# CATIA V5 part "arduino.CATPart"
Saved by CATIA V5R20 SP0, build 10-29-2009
Part number: arduino2
Bounding box of the stored display mesh (mm): x -20.66 to 70.72, y -123.76 to 0, z -5.9 to 1.5
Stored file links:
  C:\Users\user\OneDrive\바탕 화면\지혜 카티아\arduino2.CATPart
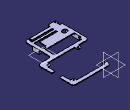
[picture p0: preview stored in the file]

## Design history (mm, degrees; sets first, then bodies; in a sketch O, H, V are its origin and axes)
Sketch1 on xy-plane, origin (0, 0, 0), H (1, 0, 0), V (0, 1, 0)
  line L1 (0, 0) -> (70.72, 0)
  line L2 (0, 0) -> (0, -12)
  line L3 (0, -12) -> (6, -12)
  line L4 (6, -12) -> (6, -6)
  line L5 (6, -6) -> (58.3, -6)
  line L6 (58.3, -6) -> (58.3, -11.85)
  line L7 (58.3, -11.85) -> (64.72, -11.85)
  line L8 (64.72, -11.85) -> (64.72, -55.31)
  line L9 (64.72, -55.31) -> (57.76, -55.31)
  line L10 (57.76, -55.31) -> (57.76, -62.09)
  line L11 (57.76, -62.09) -> (6.57, -62.09)
  line L12 (6.57, -62.09) -> (6.57, -55.52)
  line L13 (6.57, -55.52) -> (0, -55.52)
  line L14 (0, -55.52) -> (0, -68.09)
  line L15 (0, -68.09) -> (70.72, -68.09)
  line L16 (70.72, -68.09) -> (70.72, 0)
  distance L2 L8 = 64.72
  distance L1 L5 = 6
  distance L8 L16 = 6
  distance L5 L11 = 56.09
  distance L14 L8 = 64.72
  distance L11 L15 = 6
  length L9 = 6.96
  length L10 = 6.78
  length L6 = 5.85
  length L7 = 6.42
  length L3 = 6
  length L4 = 6
  length L13 = 6.57
  length L12 = 6.57
  horizontal: L1 H, L3 H, L5 H, L7 H, L9 H, L11 H, L13 H, L15 H
  vertical: L2 V, L4 V, L6 V, L8 V, L10 V, L12 V, L14 V, L16 V
Pad1: profile Sketch1, direction (0, 0, 1), length 1.5
Body1 (main body)
  Sketch2 on end face of Pad1, origin (65.2584, -7.6318, 1.5), H (1, 0, 0), V (0, 1, 0)
    point P1 (-4.1484, -1.5282)
    reference projected line E1 (5.4616, 7.6318) -> (-65.2584, 7.6318) from edge [face of Pad1 from Sketch1.L1 | end face of Pad1]
    reference projected line E2 (5.4616, -60.4582) -> (5.4616, 7.6318) from edge [face of Pad1 from Sketch1.L16 | end face of Pad1]
    distance P1 E1 = 9.16
    distance P1 E2 = 9.61
  Hole1: placed by Sketch2, at (61.11, -9.16, 1.5) direction (0, 0, -1), diameter 2.73, depth 10
  Sketch3 on end face of Pad1, origin (2.6589, -8.6433, 1.5), H (1, 0, 0), V (0, 1, 0)
    point P1 (0.7611, -0.1967)
    reference projected line E1 (-2.6589, -3.3567) -> (3.3411, -3.3567) from edge [face of Pad1 from Sketch1.L3 | end face of Pad1]
    reference projected line E2 (68.0611, -59.4467) -> (68.0611, 8.6433) from edge [face of Pad1 from Sketch1.L16 | end face of Pad1]
    distance P1 E1 = 3.16
    distance P1 E2 = 67.3
  Hole2: placed by Sketch3, at (3.42, -8.84, 1.5) direction (0, 0, -1), diameter 2.73, depth 10
  Sketch4 on end face of Pad1, origin (60.9853, -58.9482, 1.5), H (1, 0, 0), V (0, 1, 0)
    point P1 (0.1347, 0.0182)
    reference projected line E1 (9.7347, -9.1418) -> (9.7347, 58.9482) from edge [face of Pad1 from Sketch1.L16 | end face of Pad1]
    reference projected line E2 (-60.9853, -9.1418) -> (9.7347, -9.1418) from edge [face of Pad1 from Sketch1.L15 | end face of Pad1]
    distance P1 E1 = 9.6
    distance P1 E2 = 9.16
  Hole3: placed by Sketch4, at (61.12, -58.93, 1.5) direction (0, 0, -1), diameter 2.73, depth 10
  Sketch5 on end face of Pad1, origin (3.2662, -58.7862, 1.5), H (1, 0, 0), V (0, 1, 0)
    point P1 (0.1538, 0.1062)
    reference projected line E1 (3.3038, 3.2662) -> (-3.2662, 3.2662) from edge [face of Pad1 from Sketch1.L13 | end face of Pad1]
    reference projected line E2 (67.4538, -9.3038) -> (67.4538, 58.7862) from edge [face of Pad1 from Sketch1.L16 | end face of Pad1]
    distance P1 E1 = 3.16
    distance P1 E2 = 67.3
  Hole4: placed by Sketch5, at (3.42, -58.68, 1.5) direction (0, 0, -1), diameter 2.73, depth 10
  Plane1: type Offset, RefPlane start face of Pad1, Offset 0, reversed
  Sketch6 on Plane1, origin (0, 0, 0), H (1, 0, 0), V (0, 1, 0)
    line L1 (44.92, -68.09) -> (44.92, -119.15)
    line L2 (44.92, -119.15) -> (33.92, -119.15)
    line L3 (33.92, -119.15) -> (33.92, -114.15)
    line L4 (33.92, -114.15) -> (38.92, -114.15)
    line L5 (38.92, -114.15) -> (38.92, -91.15)
    line L6 (38.92, -91.15) -> (33.92, -91.15)
    line L7 (33.92, -91.15) -> (33.92, -86.15)
    line L8 (33.92, -86.15) -> (38.92, -86.15)
    point P9 (38.92, -86.15)
    line L9 (38.92, -86.15) -> (38.92, -68.09)
    line L10 (38.92, -68.09) -> (44.92, -68.09)
    reference projected line E1 (0, -68.09) -> (70.72, -68.09) from edge [face of Pad1 from Sketch1.L15 | end face of Pad1]
    reference projected line E2 (70.72, -68.09) -> (70.72, 0) from edge [face of Pad1 from Sketch1.L16 | end face of Pad1]
    reference projected line E3 (0, -68.09) -> (70.72, -68.09) from edge [face of Pad1 from Sketch1.L15 | end face of Pad1]
    length L10 = 6
    distance L1 E2 = 25.8
    length L8 = 5
    distance L8 E3 = 18.06
    length L7 = 5
    length L4 = 5
    length L3 = 5
    distance L6 L2 = 28
    vertical: L1 V, L3 V, L5 V, L7 V
    horizontal: L2 H, L4 H, L6 H, L8 H, L10 H
    coincidence: P9 L5, L10 E1
    parallelism: L9 L1
  Pad2: profile Sketch6, direction (0, 0, 1), length 1.5
  Fillet1: radius 5, on edge [face of Pad1 from Sketch1.L15 | face of Pad1 from Sketch1.L14]; edge [face of Pad1 from Sketch1.L16 | face of Pad1 from Sketch1.L15]; edge [face of Pad1 from Sketch1.L1 | face of Pad1 from Sketch1.L16]; edge [face of Pad1 from Sketch1.L2 | face of Pad1 from Sketch1.L1]
  Fillet2: radius 2, on edge [face of Pad1 from Sketch1.L10 | face of Pad1 from Sketch1.L9]; edge [face of Pad1 from Sketch1.L7 | face of Pad1 from Sketch1.L6]; edge [face of Pad1 from Sketch1.L14 | face of Pad1 from Sketch1.L13]; edge [face of Pad1 from Sketch1.L13 | face of Pad1 from Sketch1.L12]; edge [face of Pad1 from Sketch1.L3 | face of Pad1 from Sketch1.L2]; edge [face of Pad1 from Sketch1.L4 | face of Pad1 from Sketch1.L3]
  Sketch7 on face of Pad2, origin (31.9797, -88.8903, 1.5), H (1, 0, 0), V (0, 1, 0)
    point P1 (4.4403, 0.2403)
    reference projected line E1 (1.9403, 2.7403) -> (1.9403, -2.2597) from edge [face of Pad2 from Sketch6.L7 | end face of Pad2]
    reference projected line E2 (2.7403, 2.7403) -> (-2.2597, 2.7403) from edge [face of Pad2 from Sketch6.L8 | end face of Pad2]
    distance P1 E1 = 2.5
    distance P1 E2 = 2.5
  Hole5: placed by Sketch7, at (36.42, -88.65, 1.5) direction (0, 0, -1), diameter 3.7, depth 10
  Sketch8 on face of Pad2, origin (31.9024, -116.9676, 1.5), H (1, 0, 0), V (0, 1, 0)
    point P1 (4.5176, 0.3176)
    reference projected line E1 (2.0176, 2.8176) -> (2.0176, -2.1824) from edge [face of Pad2 from Sketch6.L3 | end face of Pad2]
    reference projected line E2 (2.8176, 2.8176) -> (-2.1824, 2.8176) from edge [face of Pad2 from Sketch6.L4 | end face of Pad2]
    distance P1 E1 = 2.5
    distance P1 E2 = 2.5
  Hole6: placed by Sketch8, at (36.42, -116.65, 1.5) direction (0, 0, -1), diameter 3.7, depth 10
  Fillet3: radius 5, on edge [face of Pad2 from Sketch6.L1 | face of Pad2 from Sketch6.L2]
  Fillet4: radius 5, on edge [face of Pad1 from Sketch1.L15 | face of Pad2 from Sketch6.L1]; edge [face of Pad2 from Sketch6.L9 | face of Pad1 from Sketch1.L15]
  Sketch9 on face of Pad2, origin (0, 0, 1.5), H (1, 0, 0), V (0, 1, 0)
    line L1 (64.72, -28.51) -> (67.87, -28.51)
    line L2 (67.87, -28.51) -> (67.87, -39.58)
    line L3 (67.87, -39.58) -> (64.72, -39.58)
    line L4 (64.72, -39.58) -> (64.72, -28.51)
    reference projected line E1 (64.72, -11.85) -> (64.72, -55.31) from edge [face of Pad1 from Sketch1.L8 | end face of Pad1]
    reference projected line E2 (70.72, 0) -> (0, 0) from edge [face of Pad1 from Sketch1.L1 | face of Pad2]
    length L2 = 11.07
    length L1 = 3.15
    distance L1 E2 = 28.51
    horizontal: L1 H, L3 H
    vertical: L2 V, L4 V
    coincidence: L4 E1
  Pocket1: profile Sketch9, direction (0, 0, -1), length 1.5
  Sketch10 on Plane1, origin (0, 0, 0), H (1, 0, 0), V (0, 1, 0)
    line L1 (33.92, -86.15) -> (-16.43, -86.15)
    line L2 (-16.43, -86.15) -> (-16.43, -75.8188)
    line L3 (-16.43, -75.8188) -> (-12.89, -75.8188)
    line L4 (-12.89, -75.8188) -> (-12.89, -68.09)
    line L5 (-20.66, -69.4959) -> (-20.66, -112.93)
    line L6 (-20.66, -112.93) -> (-16.28, -112.93)
    line L7 (-16.28, -112.93) -> (-16.28, -118.03)
    line L8 (-16.28, -118.03) -> (-19.05, -118.03)
    line L9 (-19.05, -118.03) -> (-19.05, -123.76)
    line L10 (-19.05, -123.76) -> (-4.08, -123.76)
    line L11 (-4.08, -123.76) -> (-4.08, -119.15)
    line L12 (-4.08, -119.15) -> (33.92, -119.15)
    line L13 (33.92, -119.15) -> (33.92, -114.15)
    line L14 (33.92, -114.15) -> (-2.85, -114.15)
    line L15 (-2.85, -114.15) -> (-2.85, -110.67)
    line L16 (-2.85, -110.67) -> (38.92, -110.67)
    line L17 (38.92, -110.67) -> (38.92, -107.15)
    line L18 (38.92, -107.15) -> (-2.85, -107.15)
    point P20 (-2.85, -107.15)
    line L19 (-2.85, -107.15) -> (-2.85, -103.67)
    line L20 (-2.85, -103.67) -> (31.43, -103.67)
    line L21 (31.43, -103.67) -> (31.43, -91.15)
    line L22 (31.43, -91.15) -> (33.92, -91.15)
    line L23 (33.92, -91.15) -> (33.92, -86.15)
    reference projected line E1 (38.92, -86.15) -> (33.92, -86.15) from edge [face of Pad2 | face of Pad2 from Sketch6.L8]
    reference projected line E2 (33.92, -91.15) -> (38.92, -91.15) from edge [face of Pad2 | face of Pad2 from Sketch6.L6]
    reference projected line E3 (38.92, -114.15) -> (33.92, -114.15) from edge [start face of Pad2 | face of Pad2 from Sketch6.L4]
    reference projected line E4 (33.92, -119.15) -> (44.92, -119.15) from edge [face of Pad2 | face of Pad2 from Sketch6.L2]
    reference projected line E5 (38.92, -91.15) -> (38.92, -114.15) from edge [start face of Pad2 | face of Pad2 from Sketch6.L5]
    reference projected line E6 (33.92, -114.15) -> (33.92, -119.15) from edge [start face of Pad2 | face of Pad2 from Sketch6.L3]
    reference projected line E7 (33.92, -86.15) -> (33.92, -91.15) from edge [start face of Pad2 | face of Pad2 from Sketch6.L7]
    reference projected line E8 (38.92, -91.15) -> (38.92, -114.15) from edge [start face of Pad2 | face of Pad2 from Sketch6.L5]
    reference projected line E9 (38.92, -91.15) -> (38.92, -114.15) from edge [start face of Pad2 | face of Pad2 from Sketch6.L5]
    line L24 (-12.89, -68.09) -> (6.57, -68.09)
    line L25 (6.57, -68.09) -> (6.57, -62.09)
    line L26 (6.57, -62.09) -> (-20.66, -62.09)
    point P27 (-20.66, -62.09)
    line L27 (-20.66, -62.09) -> (-20.66, -69.4959)
    reference projected line E10 (44.92, -68.09) -> (70.72, -68.09) from edge [face of Pad2 | face of Pad1 from Sketch1.L15]
    reference projected line E12 (38.92, -68.09) -> (38.92, -86.15) from edge [face of Pad2 | face of Pad2 from Sketch6.L9]
    reference projected line E13 (38.92, -91.15) -> (38.92, -114.15) from edge [start face of Pad2 | face of Pad2 from Sketch6.L5]
    reference projected line E14 (38.92, -91.15) -> (38.92, -114.15) from edge [start face of Pad2 | face of Pad2 from Sketch6.L5]
    reference projected line E15 (6.57, -62.09) -> (6.57, -55.52) from edge [face of Pad2 | face of Pad1 from Sketch1.L12]
    circle A1 centre (-15.0614, -73.5812) radius 1.755
    point P28 (-15.0614, -73.5812)
    circle A2 centre (-15.87, -121.46) radius 1.85
    point P29 (-15.87, -121.46)
    point P30 (-10.31, -97.76)
    ellipse A3 centre (-10.31, -97.76) semi-axes 5, 4.0824 rotation 180
    reference projected line E16 (38.92, -91.15) -> (38.92, -114.15) from edge [start face of Pad2 | face of Pad2 from Sketch6.L5]
    distance L16 L14 = 3.48
    distance L18 L20 = 3.48
    distance L18 L16 = 3.52
    distance L15 E8 = 41.77
    distance L21 E9 = 7.49
    length L25 = 6
    distance L4 E12 = 51.81
    length L3 = 3.54
    distance L11 E13 = 43
    length L11 = 4.61
    distance L9 E14 = 57.97
    length L9 = 5.73
    length L8 = 2.77
    distance L2 L5 = 4.23
    length L7 = 5.1
    radius A1 = 1.755
    radius A2 = 1.85
    distance P29 L9 = 3.18
    distance P29 L10 = 2.3
    "Radius" A3 = 5
    distance P30 L10 = 26
    distance P30 E16 = 49.23
    distance P28 L4 = 2.1714
    distance L3 L24 = 7.7288
    distance P28 L3 = 2.2376
    horizontal: L1 H, L3 H, L6 H, L8 H, L10 H, L12 H, L14 H, L16 H, L18 H, L20 H, L22 H, L24 H, L26 H
    vertical: L2 V, L4 V, L5 V, L7 V, L9 V, L11 V, L13 V, L15 V, L17 V, L19 V, L21 V, L23 V, L25 V, L27 V
    coincidence: P20 L15, L1 E1, E2 L22, L14 E3, L12 E4, L17 E5, L13 E6, L23 E7, P27 L5, L24 E10, L25 E15
    parallelism: A3 L20
  Pad3: profile Sketch10, direction (0, 0, 1), length 1.5
  Fillet5: radius 5, on edge [face of Pad3 from Sketch10.L27 | face of Pad3 from Sketch10.L26]
  Fillet6: radius 2, on edge [face of Pad3 | face of Pad2 from Sketch6.L9]; edge [face of Pad3 from Sketch10.L2 | face of Pad3]
  Fillet7: radius 2, on edge [face of Pad3 from Sketch10.L4 | face of Pad3 from Sketch10.L3]
  Fillet8: radius 2, on edge [face of Pad3 from Sketch10.L11 | face of Pad3 from Sketch10.L10]
  Sketch11 on Plane1, origin (0, 0, 0), H (1, 0, 0), V (0, 1, 0)
    line L1 (-20.66, -75.8188) -> (-16.43, -75.8188)
    line L2 (-16.43, -75.8188) -> (-16.43, -102.76)
    line L3 (-16.43, -102.76) -> (-20.66, -102.76)
    line L4 (-20.66, -102.76) -> (-20.66, -75.8188)
    reference projected line E1 (-19.05, -123.76) -> (-4.08, -123.76) from edge [face of Pad3 from Sketch10.L10 | face of Pad3]
    reference projected line E2 (-20.66, -69.4959) -> (-20.66, -112.93) from edge [face of Pad3 from Sketch10.L5 | end face of Pad3]
    reference projected point E3 (-16.43, -75.8188) from vertex [end face of Pad3 | face of Pad3 from Sketch10.L3 | face of Pad3 from Sketch10.L2]
    reference projected line E4 (-16.43, -86.15) -> (-16.43, -75.8188) from edge [face of Pad3 from Sketch10.L2 | face of Pad3]
    line L5 (40.58, -91.15) -> (44.92, -91.15)
    line L6 (44.92, -91.15) -> (44.92, -103.67)
    line L7 (40.58, -103.67) -> (40.58, -91.15)
    line L8 (44.92, -103.67) -> (40.58, -103.67)
    reference projected line E5 (-2.85, -103.67) -> (31.43, -103.67) from edge [face of Pad3 from Sketch10.L20 | end face of Pad3]
    reference projected line E6 (44.92, -119.15) -> (44.92, -68.09) from edge [face of Pad2 from Sketch6.L1 | face of Pad3]
    reference projected line E7 (33.92, -91.15) -> (38.92, -91.15) from edge [face of Pad3 | face of Pad3]
    line L9 (-19.2495, -77.234) -> (-17.723, -77.234)
    line L10 (-17.723, -77.234) -> (-17.723, -101.7129)
    line L11 (-17.723, -101.7129) -> (-19.2495, -101.7129)
    line L12 (-19.2495, -101.7129) -> (-19.2495, -77.234)
    line L13 (41.8774, -92.5069) -> (43.7755, -92.5069)
    line L14 (43.7755, -92.5069) -> (43.7755, -102.1523)
    line L15 (43.7755, -102.1523) -> (41.8774, -102.1523)
    line L16 (41.8774, -102.1523) -> (41.8774, -92.5069)
    distance L3 E1 = 21
    distance L7 L6 = 4.34
    horizontal: L1 H, L3 H, L9 H, L11 H, L13 H, L15 H
    vertical: L2 V, L4 V, L10 V, L12 V, L14 V, L16 V
    coincidence: L4 E2, L1 E3, L2 E4, L8 E5, L6 E6, L5 E7
  Pad4: profile Sketch11, direction (0, 0, -1), length 5.9
  Sketch12 on face of Pad1 from Sketch1.L8, origin (64.72, 0, 0), H (0, -1, 0), V (0, 0, 1)
    line L1 (28.51, 0) -> (26.51, 0)
    line L2 (26.51, 0) -> (26.51, -3.5)
    line L3 (26.51, -3.5) -> (41.58, -3.5)
    point P1 (41.58, 0)
    line L4 (41.58, -3.5) -> (41.58, 0)
    line L5 (41.58, 0) -> (39.58, 0)
    line L6 (39.58, 0) -> (39.58, -2)
    line L7 (39.58, -2) -> (28.51, -2)
    line L8 (28.51, -2) -> (28.51, 0)
    reference projected line E1 (39.58, 1.5) -> (39.58, 0) from edge [face of Pocket1 from Sketch9.L3 | face of Pad1 from Sketch1.L8]
    reference projected line E2 (28.51, 1.5) -> (28.51, 0) from edge [face of Pad1 from Sketch1.L8 | face of Pocket1 from Sketch9.L1]
    reference projected line E3 (39.58, 0) -> (28.51, 0) from edge [face of Pocket1 from Sketch9.L2 | face of Pad2]
    reference projected line E4 (39.58, 0) -> (28.51, 0) from edge [face of Pocket1 from Sketch9.L2 | face of Pad2]
    reference projected line E5 (39.58, 0) -> (28.51, 0) from edge [face of Pocket1 from Sketch9.L2 | face of Pad2]
    distance L4 L6 = 2
    distance L8 L2 = 2
    distance L7 E5 = 2
    distance L7 L3 = 1.5
    coincidence: P1 L1, L6 E1, L8 E2, E3 L1, L5 E4
  Pad5: profile Sketch12, direction (1, 0, 0), length 6
  Pocket2: profile face of Pocket1 from Sketch9.L2, direction along face of Pocket1 from Sketch9.L2, length 6
  Sketch13 on face of Pad5 from Sketch12.L4, origin (0, -41.58, 0), H (1, 0, 0), V (0, 0, 1)
    line L1 (64.72, 0) -> (70.72, 0)
    line L2 (70.72, 0) -> (70.72, -3.5)
    line L3 (70.72, -3.5) -> (64.72, -3.5)
    line L4 (64.72, -3.5) -> (64.72, 0)
    reference projected line E1 (65.72, 0) -> (70.72, 0) from edge [face of Pad2 | face of Fillet1]
    reference projected line E2 (64.72, -3.5) -> (64.72, 0) from edge [face of Pad5 from Sketch12.L4 | face of Pad5]
    reference projected line E3 (70.72, -3.5) -> (70.72, 0) from edge [face of Pad5 | face of Pad5 from Sketch12.L4]
    reference projected line E4 (64.72, -3.5) -> (70.72, -3.5) from edge [face of Pad5 from Sketch12.L3 | face of Pad5 from Sketch12.L4]
    horizontal: L1 H, L3 H
    vertical: L2 V, L4 V
    coincidence: L1 E1, L4 E2, L2 E3, L3 E4
  Pocket3: profile Sketch13, direction (0, 1, 0), through (limit type 6)
  Sketch14 on face of Pad3, origin (0, 0, 1.5), H (1, 0, 0), V (0, 1, 0)
    line L1 (64.72, -26.4792) -> (70.72, -26.4792)
    line L2 (70.72, -26.4792) -> (70.72, -28.51)
    line L3 (70.72, -28.51) -> (64.72, -28.51)
    line L4 (64.72, -28.51) -> (64.72, -26.4792)
    reference projected line E1 (64.72, -11.85) -> (64.72, -55.31) from edge [face of Pad5 | face of Pad3]
    reference projected line E2 (64.72, -28.51) -> (67.87, -28.51) from edge [face of Pocket2 | face of Pad3]
    reference projected line E3 (70.72, -68.09) -> (70.72, 0) from edge [face of Pad5 | face of Pad3]
    horizontal: L1 H, L3 H
    vertical: L2 V, L4 V
    coincidence: L4 E1, L3 E2, L2 E3
  Pocket4: profile Sketch14, direction (0, 0, -1), through (limit type 6)
  Sketch15 on face of Pad3, origin (0, 0, 1.5), H (1, 0, 0), V (0, 1, 0)
    line L1 (64.72, -39.58) -> (70.72, -39.58)
    line L2 (70.72, -39.58) -> (70.72, -41.226)
    line L3 (70.72, -41.226) -> (64.72, -41.226)
    line L4 (64.72, -41.226) -> (64.72, -39.58)
    reference projected line E1 (64.72, -39.58) -> (67.87, -39.58) from edge [face of Pad3 | face of Pocket2]
    reference projected line E2 (64.72, -11.85) -> (64.72, -55.31) from edge [face of Pad5 | face of Pad3]
    reference projected line E3 (70.72, -68.09) -> (70.72, 0) from edge [face of Pad5 | face of Pad3]
    horizontal: L1 H, L3 H
    vertical: L2 V, L4 V
    coincidence: L1 E1, L4 E2, L2 E3
  Pocket5: profile Sketch15, direction (0, 0, -1), through (limit type 6)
